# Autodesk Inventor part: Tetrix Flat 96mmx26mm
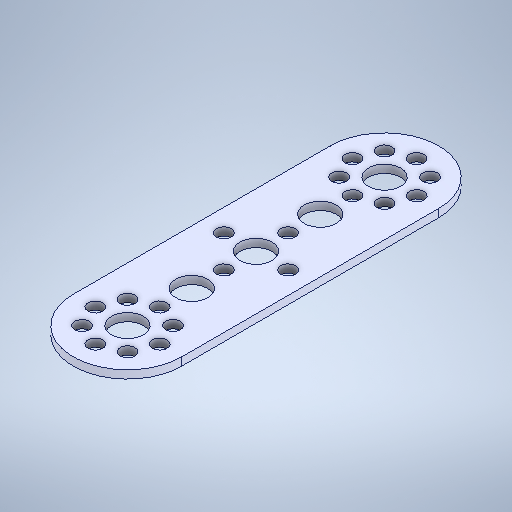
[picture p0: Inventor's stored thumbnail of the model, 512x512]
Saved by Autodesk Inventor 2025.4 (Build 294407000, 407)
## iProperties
Created: 2021-10
Part Number: Tetrix Flat 96mmx26mm
Material: Genérico
Document SubType Name: Modeling
Designer: usuario
Density: 1 g/cm^3
Appearance: Valor por defecto
Author: usuario
Sending System: SolidWorks 2016
Last Author: LENOVO
Last Saved: 2021-10-23
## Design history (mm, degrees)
feature "Boss-Extrude1"
node "Plane1"
node "Sólido1"
